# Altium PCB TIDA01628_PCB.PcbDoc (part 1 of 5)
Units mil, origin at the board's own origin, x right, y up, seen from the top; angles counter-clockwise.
Board outline 14212.6 x 5944.88 mil, 4 copper layers (Top Layer, GND, 5V, Bottom Layer), stack 60.8 mil thick; 304 components, 201 nets, 839 pads, 2143 vias.
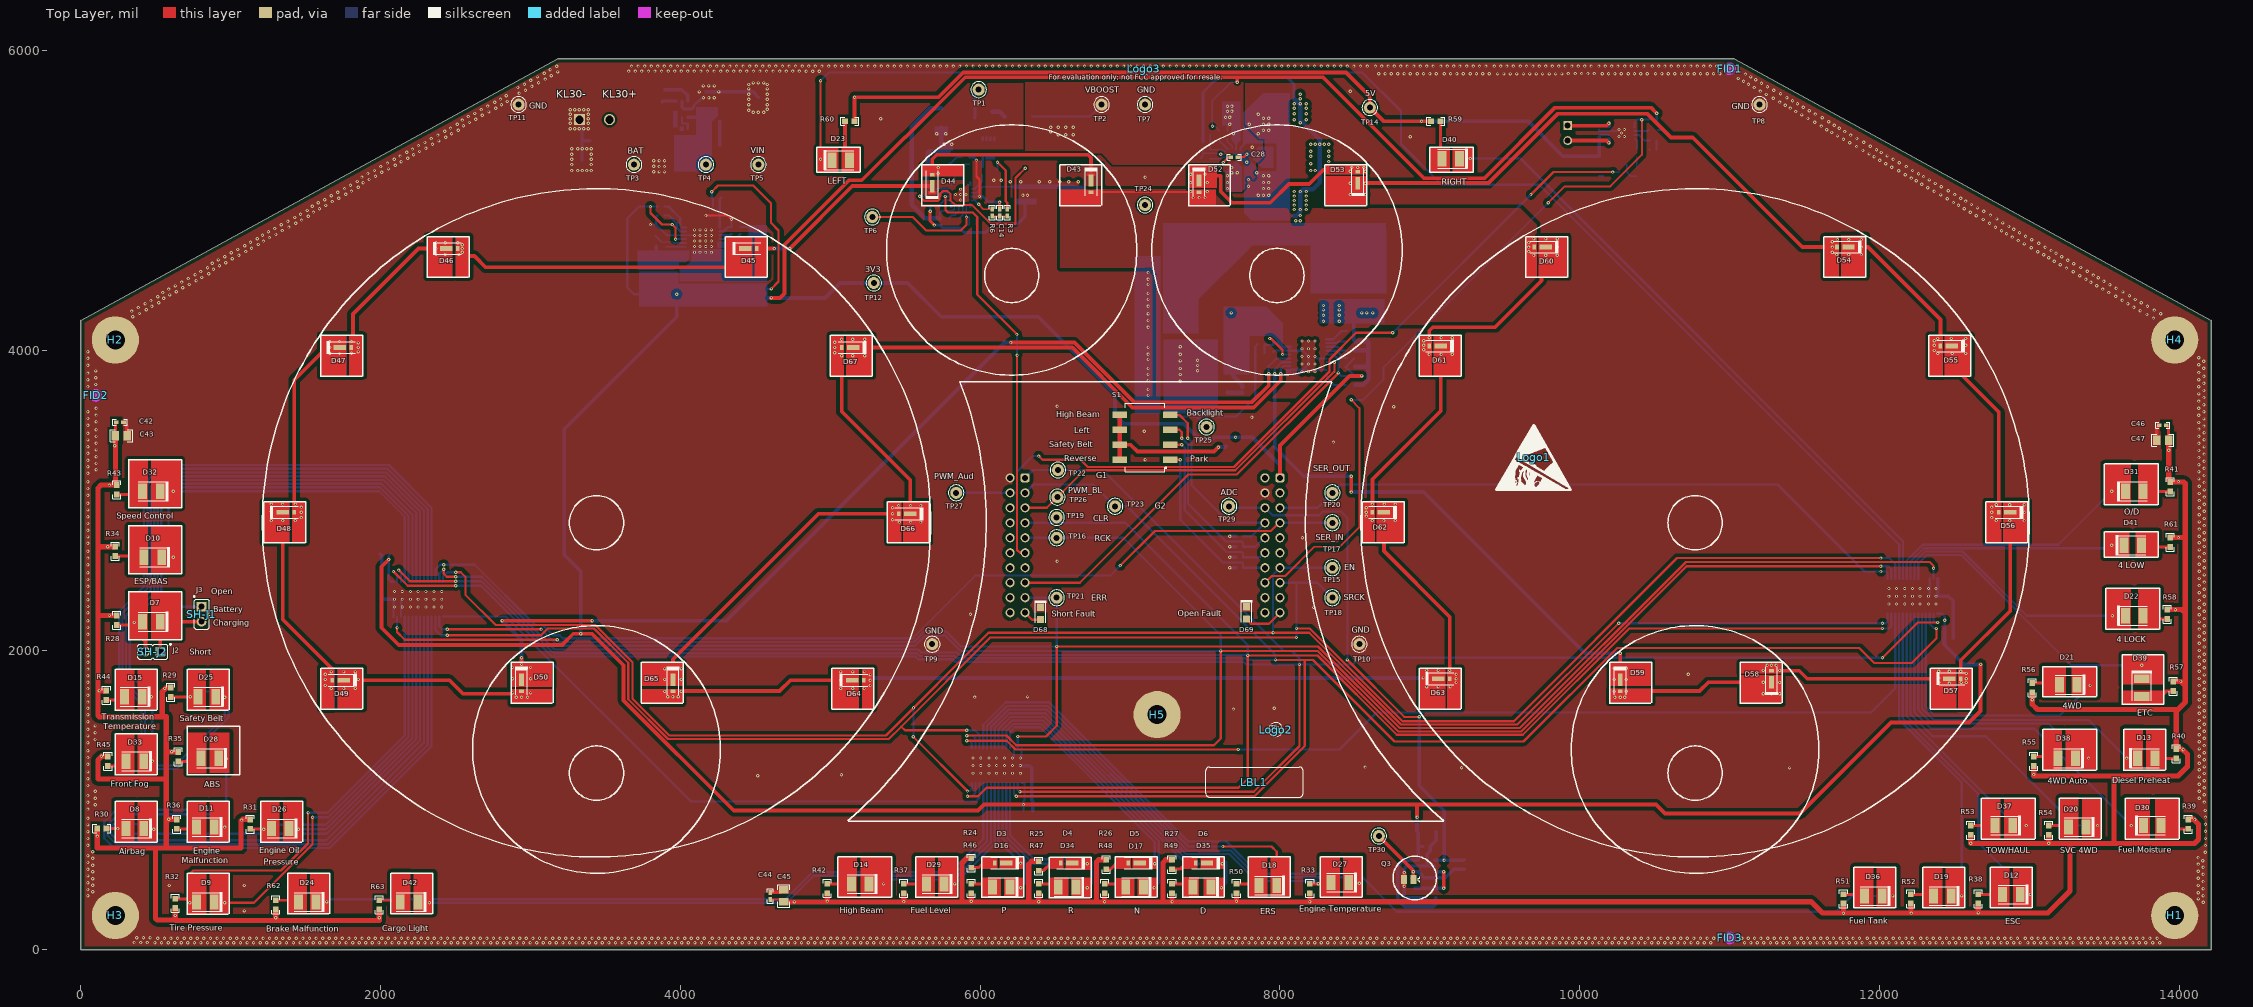
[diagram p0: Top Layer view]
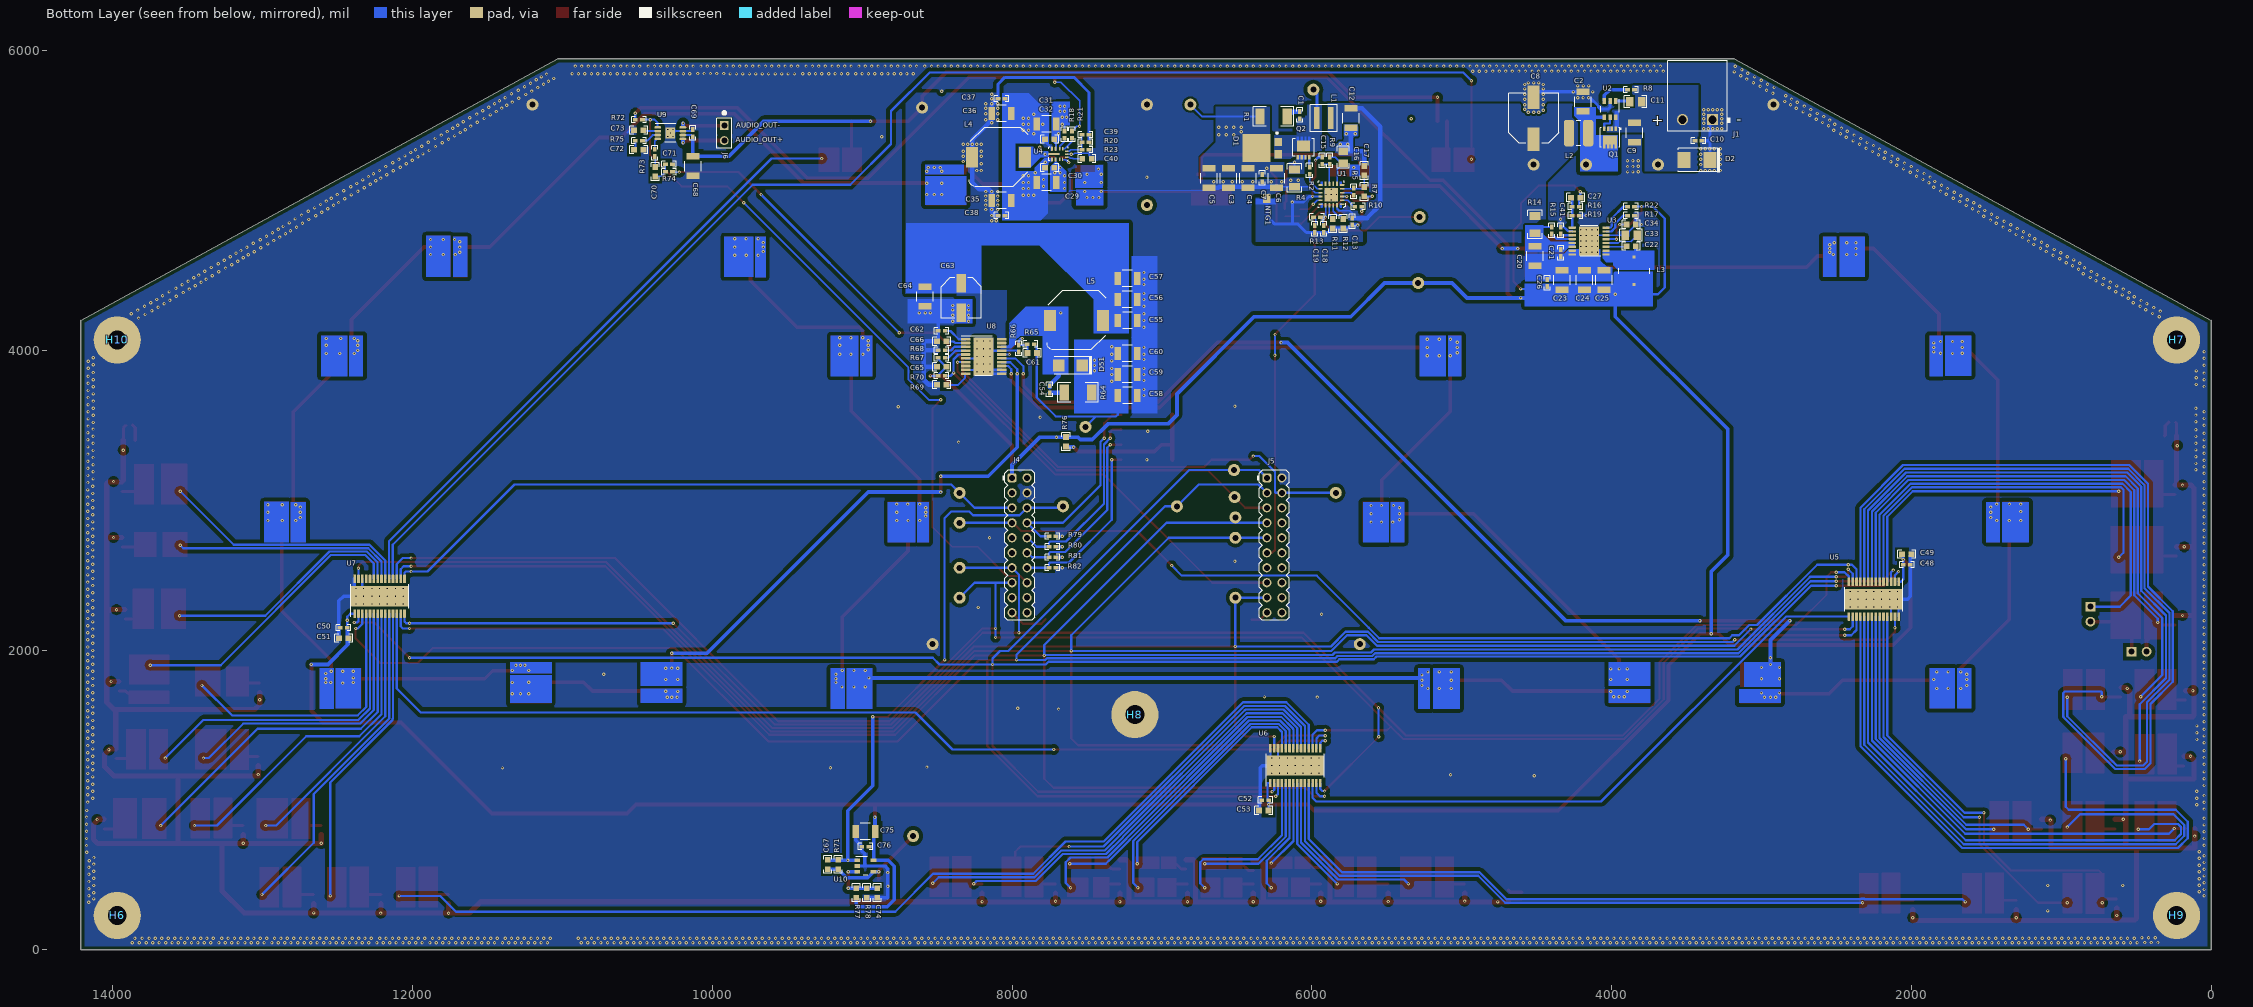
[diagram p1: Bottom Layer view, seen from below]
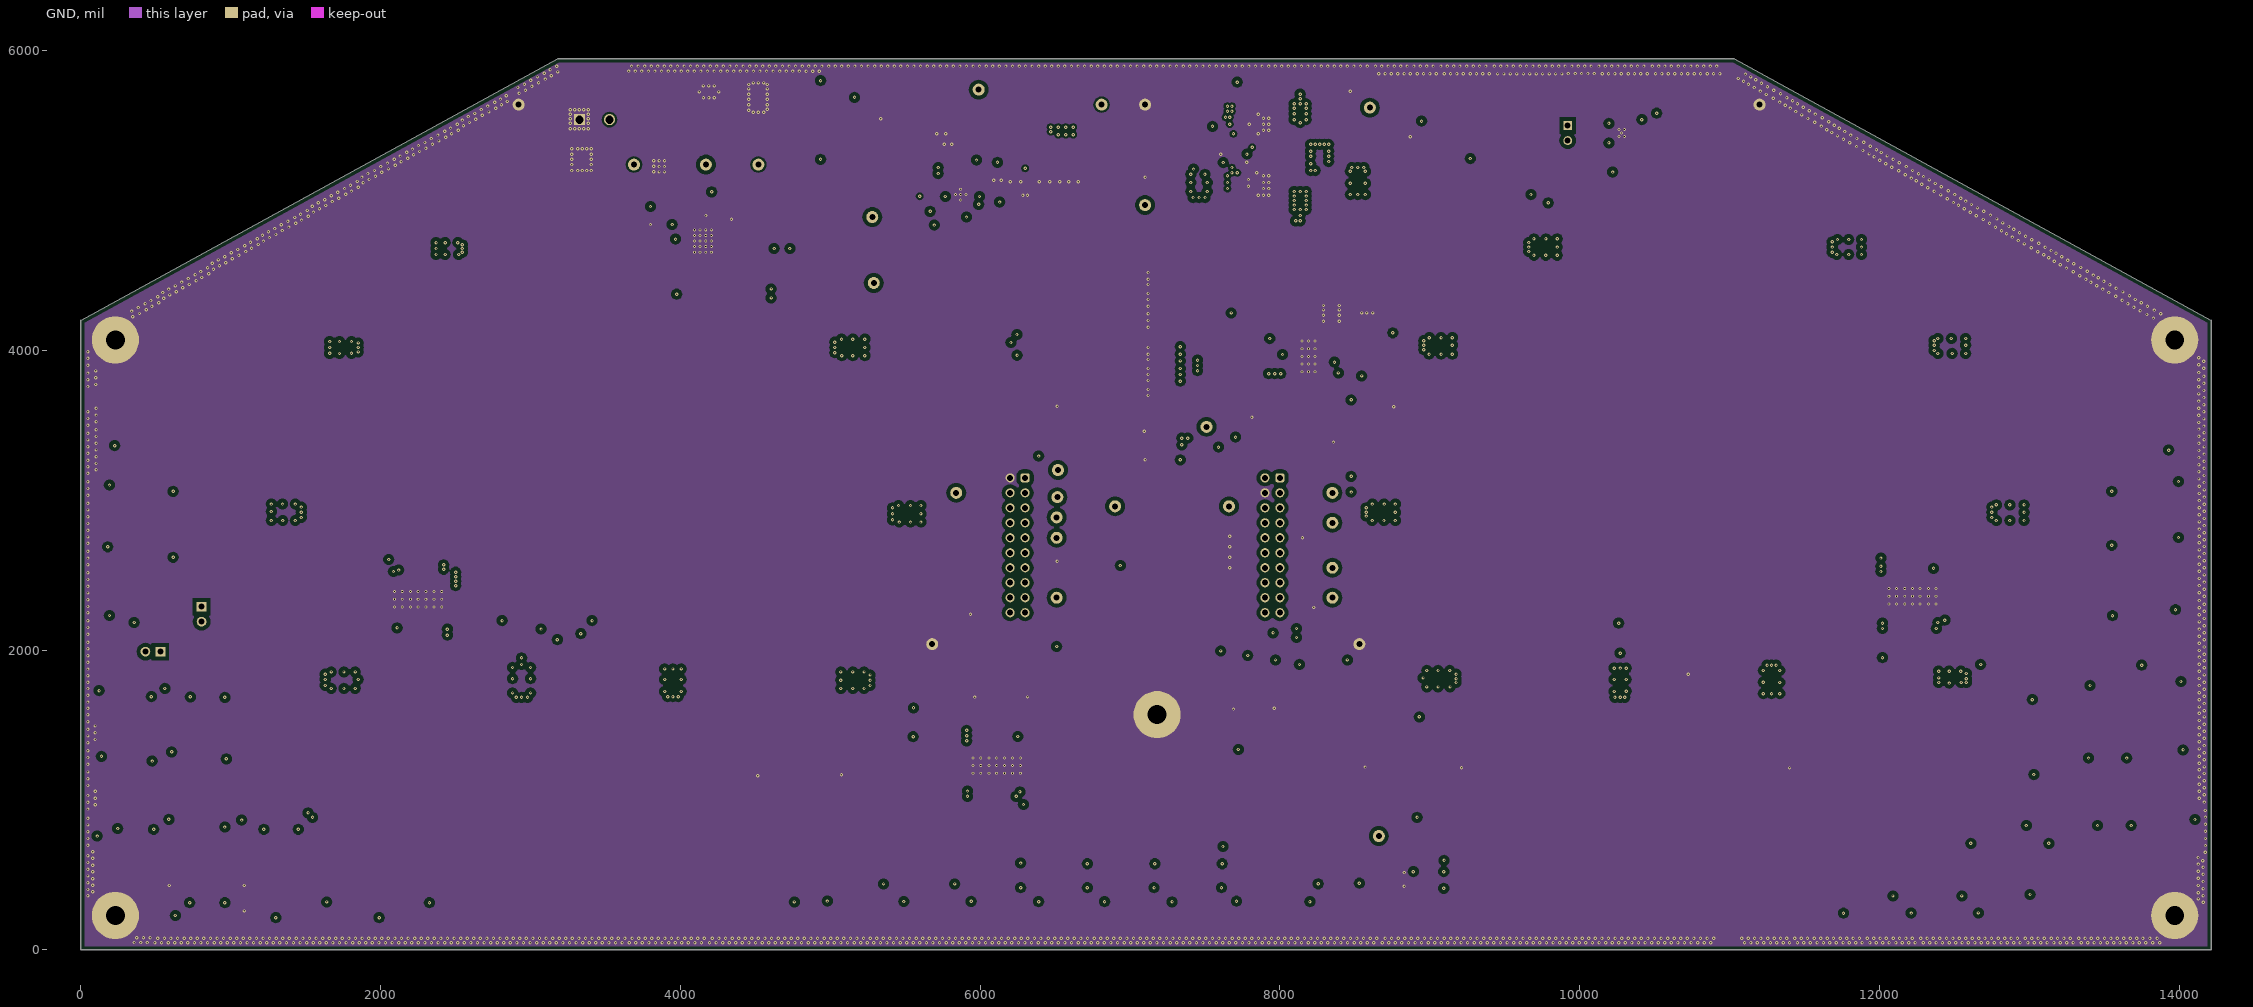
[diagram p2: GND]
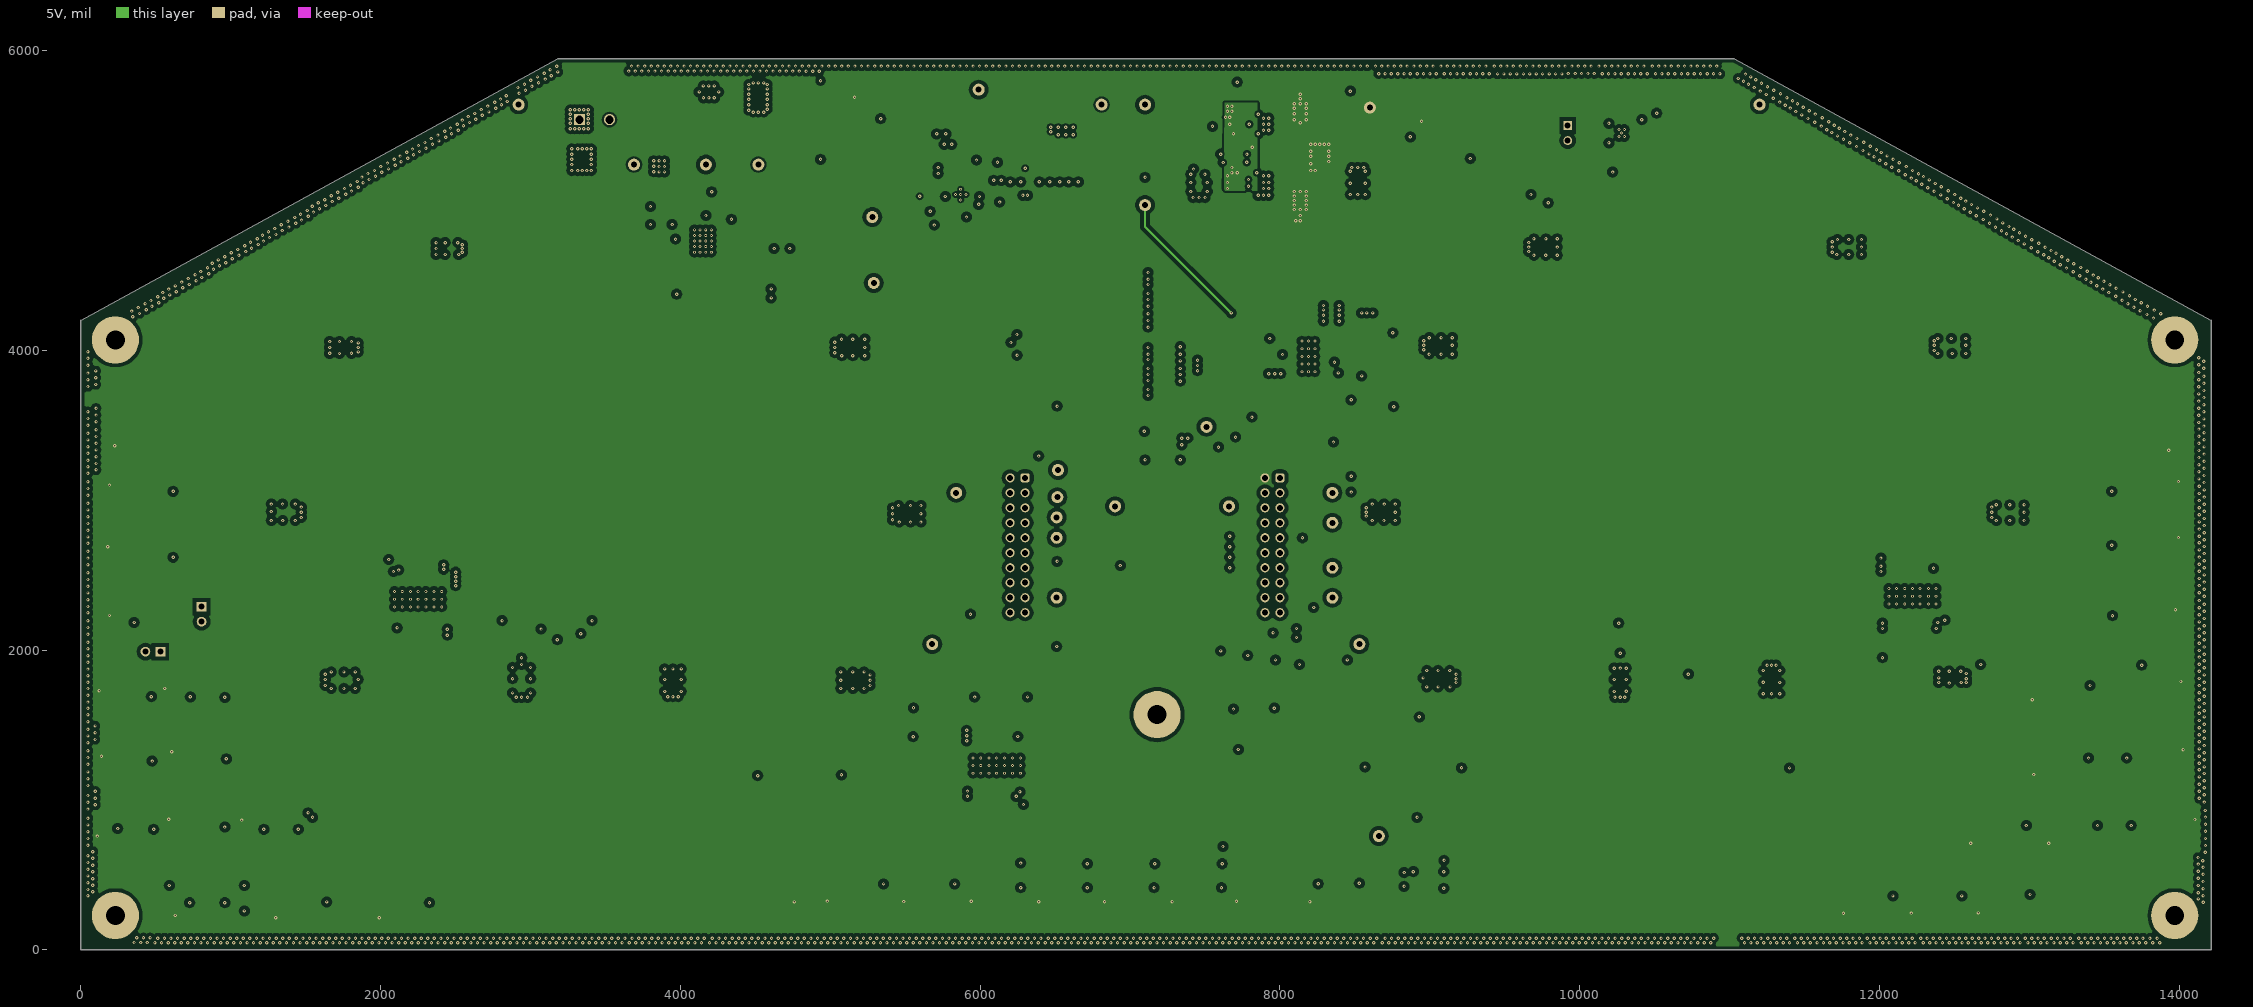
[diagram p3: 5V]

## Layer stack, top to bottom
Top Solder: solder mask 0.4, Solder Resist, Dk 3.5
Top Layer: signal copper 1.9
Pre-Preg: prepreg 11.8, 1080-FR-4 370, Dk 4.2
GND: signal copper 1.2
Core: core 31, FR4 370, Dk 4.2
5V: signal copper 1.2
Pre-Preg: prepreg 11.8, 1080-FR4 370, Dk 4.2
Bottom Layer: signal copper 1.9
Bottom Solder: solder mask 0.4, Solder Resist, Dk 3.5

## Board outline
0,0 0,4200 3179.92,5944.88 11032.68,5944.88 14212.6,4200 14212.6,0

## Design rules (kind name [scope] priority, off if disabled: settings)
AcuteAngle [All] p1: minimum=4.50000000000000E+0001 checktracksonly=FALSE
AssemblyTestPointUsage [All] p1: valid=2
BoardOutlineClearance BoardOutlineClearance_MountingHoles [OnCopper and InComponentClass('Mounting Holes')] p1: gap=40 ignorepadtopadclearanceinfootprint=FALSE
BoardOutlineClearance BoardOutlineClearance_Poly [OnCopper and IsPoly] p2: gap=25 ignorepadtopadclearanceinfootprint=FALSE
Clearance Clearance_Fidicial [HasFootprint('Fiducial10-20')] p1: gap=0 ignorepadtopadclearanceinfootprint=FALSE
Clearance Clearance_0402_COMPONENT [(InComponent('C7') OR InComponent('C10') OR InComponent('C13') OR InComponent('R8') OR InComponent('R18'))] p2: gap=15.74 ignorepadtopadclearanceinfootprint=FALSE
Clearance Clearance_Q1 [InComponent('Q1')] p3: gap=9 ignorepadtopadclearanceinfootprint=FALSE
Clearance Clearance_U1 [InComponent('U1')] p4: gap=11.81 ignorepadtopadclearanceinfootprint=FALSE
Clearance Clearance_U4 [(InNet('VBOOST') AND InComponent('U4'))] p5: gap=11.81 ignorepadtopadclearanceinfootprint=FALSE
Clearance Clearance_U2_1 [(InNet('VIN') OR InNet('VBOOST') OR InNet('KL30_Power') OR InComponent('U2'))] p6: gap=13.7 ignorepadtopadclearanceinfootprint=FALSE
Clearance Clearance_Keepouts [((IsTrack Or IsArc) And Not InPoly) And IsFree and IsKeepOut vs ((IsTrack Or IsArc) And Not InPoly) And IsFree and IsKeepOut] p7: gap=0 ignorepadtopadclearanceinfootprint=FALSE
Clearance Clearance_KL30_POWER [InNet('KL30_Power')] p8: gap=16 ignorepadtopadclearanceinfootprint=FALSE
Clearance Clearance_VBOOST [InNet('VBOOST')] p9: gap=16 ignorepadtopadclearanceinfootprint=FALSE
Clearance Clearance_VIN [InNet('VIN')] p10: gap=16 ignorepadtopadclearanceinfootprint=FALSE
Clearance Clearance_Poly [InPolygon] p11: gap=25 ignorepadtopadclearanceinfootprint=FALSE
Clearance [All] p12: gap=7.87 ignorepadtopadclearanceinfootprint=FALSE except(0: Arc-Hole Track-Hole SMDPad-Hole THPad-Hole Via-Hole Fill-Hole Poly-Hole Region-Hole Text-Hole)
Clearance Clearance_FiducialMark [IsKeepOut and InComponentClass('FiducialMark') vs IsPad and InComponentClass('FiducialMark')] p13: gap=0 ignorepadtopadclearanceinfootprint=FALSE
ComponentClearance ComponentClearance_MountingHoles_FiducialMarks [InComponentClass('Mounting Holes') vs InComponentClass('FiducialMark')] p1: gap=50 collisioncheckmode=3 verticalgap=10 showdistances=FALSE
ComponentClearance ComponentClearance_Shunt [InComponentClass('Header') vs InComponentClass('Shunt')] p2: gap=0 collisioncheckmode=3 verticalgap=0 showdistances=FALSE
ComponentClearance ComponentClearance_Logo [InComponentClass('Logo')] p3: gap=50 collisioncheckmode=3 verticalgap=10 showdistances=FALSE
ComponentClearance ComponentClearance_ScrewToNut [(HasFootprint('NY PMS 440 0025 PH')) vs (HasFootprint('Keystone_1902C'))] p4: gap=5 collisioncheckmode=3 verticalgap=10 showdistances=FALSE
ComponentClearance ComponentClearance_MountingHoles [InComponentClass('Mounting Holes')] p5: gap=250 collisioncheckmode=3 verticalgap=100000 showdistances=FALSE
ComponentClearance ComponentClearance_SmallPassives [HasFootprint('0201*') or HasFootprint('0402*') or HasFootprint('0508') or HasFootprint('0603*') or HasFootprint('0612') or HasFootprint('0805*') or HasFootprint('0815*') or HasFootprint('0830*') or HasFootprint('1206*') or HasFootprint('1210*') or HasFootprint('1808*') or HasFootprint('1812*') or HasFootprint('1825*') or HasFootprint('2010*') or HasFootprint('2220*') or HasFootprint('2225*') or HasFootprint('2512*') or HasFootprint('2728*') or HasFootprint('3518*') vs HasFootprint('0201*') or HasFootprint('0402*') or HasFootprint('0508') or HasFootprint('0603*') or HasFootprint('0612') or HasFootprint('0805*') or HasFootprint('0815*') or HasFootprint('0830*') or HasFootprint('1206*') or HasFootprint('1210*') or HasFootprint('1808*') or HasFootprint('1812*') or HasFootprint('1825*') or HasFootprint('2010*') or HasFootprint('2220*') or HasFootprint('2225*') or HasFootprint('2512*') or HasFootprint('2728*') or HasFootprint('3518*')] p6: gap=14.96 collisioncheckmode=3 verticalgap=10 showdistances=FALSE
ComponentClearance ComponentClearance_THtoSMT [IsThruComponent vs IsSMTComponent] p7: gap=40 collisioncheckmode=3 verticalgap=30 showdistances=FALSE
ComponentClearance ComponentClearance_THtoTH [IsThruComponent vs IsThruComponent] p8: gap=30 collisioncheckmode=3 verticalgap=30 showdistances=FALSE
ComponentClearance [All] p9: gap=30 collisioncheckmode=3 verticalgap=10 showdistances=FALSE
DiffPairsRouting [All] p1: maxlimit=100 minlimit=10 mostfreqgap=10 toplayer_minwidth=15 toplayer_maxwidth=15 toplayer_prefwidth=15 midlayer1_minwidth=15 midlayer1_maxwidth=15 midlayer1_prefwidth=15 midlayer2_minwidth=15 midlayer2_maxwidth=15 midlayer2_prefwidth=15 bottomlayer_minwidth=15 bottomlayer_maxwidth=15 bottomlayer_prefwidth=15 maxuncoupledlength=1000
FabricationTestPointUsage TestPointUsage [All] p1: valid=2 allowmultiple=FALSE
FabricationTestpoint Testpoint [All] p1: side=3 testpointundercomponent=TRUE minsize=40 maxsize=100 preferedsize=60 minholesize=0 maxholesize=40 preferedholesize=32 testpointgrid=1 allowsidetop=TRUE allowsidebottom=TRUE usegrid=TRUE gridtolerance=0.01
FanoutControl Fanout_LCC [IsLCC] p1: bgadir=Out bgaviamode=Centered fanoutstyle=Auto fanoutdirection=Alternating viagrid=1 // Fanout_LCC (Default Rule)
FanoutControl Fanout_BGA [IsBGA] p2: bgadir=Out bgaviamode=Centered fanoutstyle=Auto fanoutdirection=Alternating viagrid=1 // Fanout_BGA (Default Rule)
FanoutControl Fanout_Default [All] p4: bgadir=Out bgaviamode=Centered fanoutstyle=Auto fanoutdirection=Alternating viagrid=1 // Fanout_Default (Default Rule)
FanoutControl Fanout_Small [(CompPinCount < 5)] p5: bgadir=Out bgaviamode=Centered fanoutstyle=Auto fanoutdirection=OutThenIn viagrid=1 // Fanout_Small (Default Rule)
HoleSize [All] p1: absolutevalues=TRUE maxlimit=251 minlimit=7.87 maxpercent=80.000 minpercent=20.000
MinimumAnnularRing MinimumAnnularRing_ThermalPadVias [IsVia and InAnyComponent] p1: minimumring=5.91
MinimumAnnularRing [All] p2: minimumring=6
MinimumSolderMaskSliver MinimumSolderMaskSliver_Logo [InComponentClass('Logo') vs InComponentClass('Logo')] p1: minsoldermaskwidth=0.7
MinimumSolderMaskSliver [All] p2: minsoldermaskwidth=3.94
PlaneConnect [All] p1: planeconnectstyle=Direct reliefexpansion=10 reliefentries=4 reliefconductorwidth=10 reliefairgap=10
PolygonConnect [All] p1: connectstyle=Direct reliefconductorwidth=10 reliefentries=4 polygonreliefangle="90 Angle" airgapwidth=10
RoutingVias ThermalPadVias [IsVia and InAnyComponent] p1: holewidth=7.87 width=19.68 viastyle="Through Hole" minholewidth=7.87 minwidth=19.68 maxholewidth=12.99 maxwidth=23.62
RoutingVias [All] p2: holewidth=16 width=34 viastyle="Through Hole" minholewidth=7.87 minwidth=26 maxholewidth=40 maxwidth=65
ShortCircuit ShortCircuit_U1 [InComponent('U1')] p1: allowed=TRUE
ShortCircuit [All] p2: allowed=FALSE
SilkToBoardRegionClearance [Not ((IsComment or IsDesignator) And (Hide <> 'False')) and not InRegion(1000,500,4000,800)] p1:
SilkToSilkClearance SilkToSilkClearance_Pb-FreeLogo [(HasFootprint('Pb-Free_Overlay_Medium') OR HasFootprint('Pb-Free_Overlay_Small')) vs (HasFootprint('Pb-Free_Overlay_Medium') OR HasFootprint('Pb-Free_Overlay_Small'))] p1: silktosilkclearance=0
SilkToSilkClearance [All] p2: silktosilkclearance=4
SilkToSolderMaskClearance SilkToComponentPadClearance_DIODE [InComponent('D2')or InComponent('D51')or InComponent('D68')or InComponent('D69')] p1: minsilkscreentomaskgap=3 clearancetoexposedcopper=TRUE
SilkToSolderMaskClearance SilkToComponentPadClearance [(IsPad or IsFill or IsRegion) and InAnycomponent] p2: minsilkscreentomaskgap=5 clearancetoexposedcopper=TRUE
SilkToSolderMaskClearance "Silk to Solder Mask Opening" [All] p3: minsilkscreentomaskgap=4 clearancetoexposedcopper=FALSE
SolderMaskExpansion [All] p1: expansion=1.97
Width [All] p1: maxlimit=100 minlimit=6 preferedwidth=10 checkconnectedcopper=TRUE
14 further rules are at their usual default settings.

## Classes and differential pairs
component class AssemblyNote: ZZ1 ZZ2 ZZ3 ZZ4
component class FiducialMark: FID1 FID2 FID3
component class Header: J2 J3 J4 J5 J6
component class Label: LBL1
component class "Mounting Holes": H1 H2 H3 H4 H5
component class SHUNT: SH-J1 SH-J2
component class TIDA01628_Hardware: !PCB1 FID1 FID2 FID3 H1 H2 H3 H4 H5 H6 H7 H8 H9 H10 LBL1 Logo1 Logo2 Logo3 SH-J1 SH-J2 ZZ1 ZZ2 ZZ3 ZZ4
component class TIDA01628_Power: C1 C2 C3 C4 C5 C6 C7 C8 C9 C10 C11 C12 C13 C14 C15 C16 C17 C18 C19 C20 C21 C22 C23 C24 C25 C26 C27 C28 C29 C30 C31 C32 C33 C34 C35 C36 C37 C38 C39 C40 C41 D1 D2 J1 L1 L2 L3 L4 NTG1 Q1 Q2 R1 R2 R3 R4 R5 R6 R7 R8 R9 R10 R11 R12 R13 R14 R15 R16 R17 R18 R19 R20 R21 R22 R23 TP1 TP2 TP3 TP4 TP5 TP6 TP7 TP8 TP9 TP10 TP11 TP12 TP14 U1 U2 U3 U4
component class TIDA01628_Signal: C54 C55 C56 C57 C58 C59 C60 C61 C62 C63 C64 C65 C66 C67 C68 C69 C70 C71 C72 C73 C74 C75 C76 D43 D44 D45 D46 D47 D48 D49 D50 D51 D52 D53 D54 D55 D56 D57 D58 D59 D60 D61 D62 D63 D64 D65 D66 D67 D68 D69 J4 J5 J6 L5 Q3 R64 R65 R66 R67 R68 R69 R70 R71 R72 R73 R74 R75 R76 R77 R78 R79 R80 R81 R82 S1 TP24 TP25 TP26 TP27 TP29 TP30 U8 U9 U10
component class TIDA01628_Telltale: C42 C43 C44 C45 C46 C47 C48 C49 C50 C51 C52 C53 D3 D4 D5 D6 D7 D8 D9 D10 D11 D12 D13 D14 D15 D16 D17 D18 D19 D20 D21 D22 D23 D24 D25 D26 D27 D28 D29 D30 D31 D32 D33 D34 D35 D36 D37 D38 D39 D40 D41 D42 J2 J3 R24 R25 R26 R27 R28 R29 R30 R31 R32 R33 R34 R35 R36 R37 R38 R39 R40 R41 R42 R43 R44 R45 R46 R47 R48 R49 R50 R51 R52 R53 R54 R55 R56 R57 R58 R59 R60 R61 R62 R63 TP15 TP16 TP17 TP18 TP19 TP20 TP21 TP22 TP23 U5 U6 U7

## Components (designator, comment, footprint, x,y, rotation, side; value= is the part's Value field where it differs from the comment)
C1 "DNP" 0402 6080,5570 r270 bottom value=2200pF
C2 "UMK325AB7106KMHT" 1210_280 4190,5660 r90 bottom value=10uF
C3 "UMK325AB7106KMHT" 1210_280 6555,5150 r270 bottom value=10uF
C4 "UMK325AB7106KMHT" 1210_280 6425,5150 r270 bottom value=10uF
C5 "UMK325AB7106KMHT" 1210_280 6685,5150 r270 bottom value=10uF
C6 "UMK325AB7106KMHT" 1210_280 6235.12,5150 r270 bottom value=10uF
C7 "GCM155R71H104KE02D" 0402 6330,5150 r270 bottom value=0.1uF
C8 "EEE-FK1H101P" SM_RADIAL_F 4520,5550 r90 bottom value=100uF
C9 "UMK325AB7106KMHT" 1210_280 3848,5453 r270 bottom value=10uF
C10 "GCM155R71H104KE02D" 0402 3420,5400 r180 bottom value=0.1uF
C11 "C2012X5R1H225K125AB" 0805_HV 3840,5660 r0 bottom value=2.2uF
C12 "UMK325AB7106KMHT" 1210_280 5740,5550 r270 bottom value=10uF
C13 "GCM155R71H104KE02D" 0402 5730,4860 r270 bottom value=0.1uF
C14 "GRM155R71H102KA01D" 0402 6130,4920 r90 top value=1000pF
C15 "GCM155R71H104KE02D" 0402 5930,5266.38 r90 bottom value=0.1uF
C16 "GCM21BR71C475KA73K" 0805_HV 5790,5290 r90 bottom value=4.7uF
C17 "GCM188R71C105KA64D" 0603 5650,5200 r270 bottom value=1uF
C18 "CGA2B2C0G1H151J050BA" 0402 5920,4810 r270 bottom value=150pF
C19 "CGA2B2X7R1H472K050BA" 0402 5980,4810 r270 bottom value=4700pF
C20 "UMK325AB7106KMHT" 1210_280 4510,4630 r270 bottom value=10uF
C21 "GCM155R71H104KE02D" 0402 4340,4650 r270 bottom value=0.1uF
C22 "CGA3E3X7R1H224K080AB" 0603 3870,4695 r180 bottom value=0.22uF
C23 "CGA6P1X7R1C226M250AC" 1210_280 4330,4470 r90 bottom value=22uF
C24 "CGA6P1X7R1C226M250AC" 1210_280 4180,4470 r90 bottom value=22uF
C25 "CGA6P1X7R1C226M250AC" 1210_280 4050,4470 r90 bottom value=22uF
C26 "CGA2B3X7R1H103K050BB" 0402 4430,4450 r90 bottom value=0.01uF
C27 "CGA3E3X7R1H224K080AB" 0603 4240,5020 r0 bottom value=0.22uF
C28 "GCM155R71H104KE02D" 0402 7695,5290 r0 top value=0.1uF
C29 "UMK325AB7106KMHT" 1210_280 7770,5120 r0 bottom value=10uF
C30 "CGA3E3X7R1H224K080AB" 0603 7750,5220 r0 bottom value=0.22uF
C31 "UMK325AB7106KMHT" 1210_280 7770,5510 r0 bottom value=10uF
C32 "CGA3E3X7R1H224K080AB" 0603 7750,5410 r0 bottom value=0.22uF
C33 "GCM21BR71C475KA73K" 0805_HV 3870,4770 r180 bottom value=4.7uF
C34 "GCM188R71C105KA64D" 0603 3870,4840 r180 bottom value=1uF
C35 "CGA6P1X7R1C226M250AC" 1210_280 8070,5000 r180 bottom value=22uF
C36 "CGA6P1X7R1C226M250AC" 1210_280 8070,5580 r180 bottom value=22uF
C37 "GCM155R71H104KE02D" 0402 8070,5680 r180 bottom value=0.1uF
C38 "GCM155R71H104KE02D" 0402 8070,4900 r180 bottom value=0.1uF
C39 "CGA2B3X7R1H103K050BB" 0402 7510,5440 r0 bottom value=0.01uF
C40 "GCM188R71C105KA64D" 0603 7500,5280 r180 bottom value=1uF
C41 "CGA2B3X7R1H153K050BB" 0402 4340,4800 r90 bottom value=0.015uF
C42 "GCM155R71H104KE02D" 0402 260,3520 r0 top value=0.1uF
C43 "GCM21BR71C475KA73K" 0805_HV 270,3430 r0 top value=4.7uF
C44 "GCM155R71H104KE02D" 0402 4600,360 r90 top value=0.1uF
C45 "GCM21BR71C475KA73K" 0805_HV 4690,360 r90 top value=4.7uF
C46 "GCM155R71H104KE02D" 0402 13890,3500 r180 top value=0.1uF
C47 "GCM21BR71C475KA73K" 0805_HV 13890,3400 r180 top value=4.7uF
C48 "GCM155R71H104KE02D" 0402 2030,2570 r180 bottom value=0.1uF
C49 "GCM188R71C105KA64D" 0603 2030,2640 r180 bottom value=1uF
C50 "GCM155R71H104KE02D" 0402 12460,2150 r0 bottom value=0.1uF
C51 "GCM188R71C105KA64D" 0603 12460,2080 r0 bottom value=1uF
C52 "GCM155R71H104KE02D" 0402 6310,1000 r0 bottom value=0.1uF
C53 "GCM188R71C105KA64D" 0603 6320,930 r0 bottom value=1uF
C54 "DNP" 0402 7750,3740 r90 bottom value=2200pF
C55 "UMK325AB7106KMHT" 1210_280 7230,4200 r180 bottom value=10uF
C56 "UMK325AB7106KMHT" 1210_280 7230.31,4339.69 r180 bottom value=10uF
C57 "UMK325AB7106KMHT" 1210_280 7230.31,4479.69 r180 bottom value=10uF
C58 "UMK325AB7106KMHT" 1210_280 7230,3700 r180 bottom value=10uF
C59 "UMK325AB7106KMHT" 1210_280 7230.31,3839.69 r180 bottom value=10uF
C60 "UMK325AB7106KMHT" 1210_280 7230.31,3979.69 r180 bottom value=10uF
C61 "06035A4R7CAT2A" 0603 7866,3982.8 r0 bottom value=4.7pF
C62 "GCM155R71H104KE02D" 0402 8470,4130 r0 bottom value=0.1uF
C63 "EEE-FK1V330P" SM_RADIAL_D 8340,4350 r270 bottom value=33uF
C64 "UMK325AB7106KMHT" 1210_280 8580,4360 r270 bottom value=10uF
C65 "GCM188R71C105KA64D" 0603 8470,3890 r0 bottom value=1uF
C66 "GCM188R71C105KA64D" 0603 8469.69,4060 r0 bottom value=1uF
C67 "C1608C0G1H101J080AE" 0603 9228.7,570 r270 bottom value=100pF
C68 "UMK325AB7106KMHT" 1210_280 10130,5230 r270 bottom value=10uF
C69 "GCM155R71H104KE02D" 0402 10130,5450 r90 bottom value=0.1uF
C70 "GCM188R71C474KA55D" 0603 10380,5193 r270 bottom value=0.47uF
C71 "GCM155R71E103KA37D" 0402 10289,5242 r180 bottom value=0.01uF
C72 "GCM188R71C474KA55D" 0603 10490,5340 r180 bottom value=0.47uF
C73 "CGA3E3X7R1H224K080AB" 0603 10490,5470 r0 bottom value=0.22uF
C74 "GCM188R71C105KA64D" 0603 8898.7,380 r270 bottom value=1uF
C75 "UMK325AB7106KMHT" 1210_280 8978.7,790 r0 bottom value=10uF
C76 "GCM155R71H104KE02D" 0402 8978.7,690 r0 bottom value=0.1uF
D1 "V10P6-M3/87A" TO-277A 6295.12,5350 r270 bottom value=60V
D2 "SMBJ33CA-13-F" SMB 3430,5270 r0 bottom value=33V
D3 "KW DPLS32.EC-6H6J-4F8G-1" KW_DPLS32_EC_White 6150,580 r0 top value=White
D4 "KW DPLS32.EC-6H6J-4F8G-1" KW_DPLS32_EC_White 6590,580 r0 top value=White
D5 "KW DPLS32.EC-6H6J-4F8G-1" KW_DPLS32_EC_White 7040,580 r0 top value=White
D6 "KW DPLS32.EC-6H6J-4F8G-1" KW_DPLS32_EC_White 7490,580 r0 top value=White
D7 "LS T67K-J1L2-1-Z" LS_T67K_Red 470,2190 r90 top value=Red
D8 "LS T67K-J1L2-1-Z" LS_T67K_Red 360,810 r90 top value=Red
D9 "LS T67K-J1L2-1-Z" LS_T67K_Red 830,320 r90 top value=Red
D10 "LY T67K-J2M1-26-Z" LY_T67K_Yellow 480,2620 r90 top value=Yellow
D11 "LY T67K-J2M1-26-Z" LY_T67K_Yellow 830,820 r90 top value=Yellow
D12 "LY T67K-J2M1-26-Z" LY_T67K_Yellow 12880,370 r90 top value=Yellow
D13 "LY T67K-J2M1-26-Z" LY_T67K_Yellow 13780,1280 r270 top value=Yellow
D14 "LB T673-L2P1-25-Z" LB_T673_Blue 5200,440 r90 top value=Blue
D15 "LG T67K-G2K1-24-Z" LG_T67K_Green 350,1690 r90 top value=Green
D16 "LG T67K-G2K1-24-Z" LG_T67K_Green 6140,420 r90 top value=Green
D17 "LG T67K-G2K1-24-Z" LG_T67K_Green 7030,420 r90 top value=Green
D18 "LG T67K-G2K1-24-Z" LG_T67K_Green 7920,430 r90 top value=Green
D19 "LG T67K-G2K1-24-Z" LG_T67K_Green 12420,360 r90 top value=Green
D20 "LG T67K-G2K1-24-Z" LG_T67K_Green 13320,820 r90 top value=Green
D21 "LG T67K-G2K1-24-Z" LG_T67K_Green 13260,1770 r90 top value=Green
D22 "LG T67K-G2K1-24-Z" LG_T67K_Green 13700,2230 r270 top value=Green
D23 "LG T67K-G2K1-24-Z" LG_T67K_Green 5070,5270 r270 top value=Green
D24 "LG T67K-G2K1-24-Z" LG_T67K_Green 1510,320 r90 top value=Green
D25 "LS T67K-J1L2-1-Z" LS_T67K_Red 840,1690 r90 top value=Red
D26 "LS T67K-J1L2-1-Z" LS_T67K_Red 1330,810 r90 top value=Red
D27 "LS T67K-J1L2-1-Z" LS_T67K_Red 8400,450 r90 top value=Red
D28 "LY T67K-J2M1-26-Z" LY_T67K_Yellow 860,1280 r90 top value=Yellow
D29 "LY T67K-J2M1-26-Z" LY_T67K_Yellow 5700,440 r90 top value=Yellow
D30 "LY T67K-J2M1-26-Z" LY_T67K_Yellow 13820,830 r270 top value=Yellow
D31 "LY T67K-J2M1-26-Z" LY_T67K_Yellow 13700,3060 r270 top value=Yellow
D32 "LG T67K-G2K1-24-Z" LG_T67K_Green 470,3060 r90 top value=Green
D33 "LG T67K-G2K1-24-Z" LG_T67K_Green 360,1260 r90 top value=Green
D34 "LG T67K-G2K1-24-Z" LG_T67K_Green 6580,420 r90 top value=Green
D35 "LG T67K-G2K1-24-Z" LG_T67K_Green 7480,420 r90 top value=Green
D36 "LG T67K-G2K1-24-Z" LG_T67K_Green 11960,360 r90 top value=Green
D37 "LG T67K-G2K1-24-Z" LG_T67K_Green 12830,830 r90 top value=Green
D38 "LG T67K-G2K1-24-Z" LG_T67K_Green 13250,1280 r90 top value=Green
D39 "LG T67K-G2K1-24-Z" LG_T67K_Green 13750,1750 r180 top value=Green
D40 "LG T67K-G2K1-24-Z" LG_T67K_Green 9140,5280 r90 top value=Green
D41 "LG T67K-G2K1-24-Z" LG_T67K_Green 13690,2700 r270 top value=Green
D42 "LG T67K-G2K1-24-Z" LG_T67K_Green 2190,320 r90 top value=Green
D43 "KW DPLS32.EC-6H6J-4F8G-1" KW_DPLS32_EC_White 6740,5110 r90 top value=White
D44 "KW DPLS32.EC-6H6J-4F8G-1" KW_DPLS32_EC_White 5680,5120 r270 top value=White
D45 "KW DPLS32.EC-6H6J-4F8G-1" KW_DPLS32_EC_White 4457.01,4680 r180 top value=White
D46 "KW DPLS32.EC-6H6J-4F8G-1" KW_DPLS32_EC_White 2460,4680 r180 top value=White
D47 "KW DPLS32.EC-6H6J-4F8G-1" KW_DPLS32_EC_White 1750,4020 r180 top value=White
D48 "KW DPLS32.EC-6H6J-4F8G-1" KW_DPLS32_EC_White 1370,2920 r180 top value=White
D49 "KW DPLS32.EC-6H6J-4F8G-1" KW_DPLS32_EC_White 1730,1800 r0 top value=White
D50 "KW DPLS32.EC-6H6J-4F8G-1" KW_DPLS32_EC_White 2940,1780 r90 top value=White
D51 "SSA36" SMA 7610,3900 r0 bottom value=60V
D52 "KW DPLS32.EC-6H6J-4F8G-1" KW_DPLS32_EC_White 7460,5110 r90 top value=White
D53 "KW DPLS32.EC-6H6J-4F8G-1" KW_DPLS32_EC_White 8520,5140 r270 top value=White
D54 "KW DPLS32.EC-6H6J-4F8G-1" KW_DPLS32_EC_White 11770,4690 r0 top value=White
D55 "KW DPLS32.EC-6H6J-4F8G-1" KW_DPLS32_EC_White 12460,4030 r0 top value=White
D56 "KW DPLS32.EC-6H6J-4F8G-1" KW_DPLS32_EC_White 12850,2920 r0 top value=White
D57 "KW DPLS32.EC-6H6J-4F8G-1" KW_DPLS32_EC_White 12490,1810 r180 top value=White
D58 "KW DPLS32.EC-6H6J-4F8G-1" KW_DPLS32_EC_White 11280,1810 r270 top value=White
D59 "KW DPLS32.EC-6H6J-4F8G-1" KW_DPLS32_EC_White 10270,1780 r90 top value=White
D60 "KW DPLS32.EC-6H6J-4F8G-1" KW_DPLS32_EC_White 9750,4690 r0 top value=White
D61 "KW DPLS32.EC-6H6J-4F8G-1" KW_DPLS32_EC_White 9050,4030 r0 top value=White
D62 "KW DPLS32.EC-6H6J-4F8G-1" KW_DPLS32_EC_White 8670,2920 r0 top value=White
D63 "KW DPLS32.EC-6H6J-4F8G-1" KW_DPLS32_EC_White 9080,1810 r180 top value=White
D64 "KW DPLS32.EC-6H6J-4F8G-1" KW_DPLS32_EC_White 5170,1800 r180 top value=White
D65 "KW DPLS32.EC-6H6J-4F8G-1" KW_DPLS32_EC_White 3950,1780 r90 top value=White
D66 "KW DPLS32.EC-6H6J-4F8G-1" KW_DPLS32_EC_White 5510,2910 r0 top value=White
D67 "KW DPLS32.EC-6H6J-4F8G-1" KW_DPLS32_EC_White 5130,4020 r0 top value=White
D68 "LTST-C170KRKT" LED_LTST-C170_Red 6402,2245 r90 top value=Red
D69 "LTST-C170KRKT" LED_LTST-C170_Red 7776.77,2248.25 r90 top value=Red
FID1 "Fiducial" Fiducial10-20 11000,5880 r90 top
FID2 "Fiducial" Fiducial10-20 100,3700 r90 top
FID3 "Fiducial" Fiducial10-20 11000,80 r90 top
H1 "NY PMS 440 0025 PH" "NY PMS 440 0025 PH" 13970,230 r0 top locked
H2 "NY PMS 440 0025 PH" "NY PMS 440 0025 PH" 230,4070 r0 top locked
H3 "NY PMS 440 0025 PH" "NY PMS 440 0025 PH" 230,230 r0 top locked
H4 "NY PMS 440 0025 PH" "NY PMS 440 0025 PH" 13970,4070 r0 top
H5 "NY PMS 440 0025 PH" "NY PMS 440 0025 PH" 7180.23,1569.99 r0 top
H6 "1902C" Keystone_1902C 13969.77,230.01 r180 bottom
H7 "1902C" Keystone_1902C 230,4070 r180 bottom
H8 "1902C" Keystone_1902C 7180,1570 r180 bottom locked
H9 "1902C" Keystone_1902C 229.77,230.01 r180 bottom
H10 "1902C" Keystone_1902C 13970,4070 r0 bottom locked
J1 "1759017" Phoenix_1759017 3426.55,5540 r0 bottom
J2 "PBC02SAAN" Sullins_PBC02SAAN 480,1990 r270 top
J3 "PBC02SAAN" Sullins_PBC02SAAN 805.09,2240 r0 top
J4 "PEC10DAAN" SULLINS_PEC10DAAN 7950,2700 r180 bottom locked
J5 "PEC10DAAN" SULLINS_PEC10DAAN 6250,2700 r180 bottom locked
J6 "5-146261-1" CONN_5-146261-1 9920,5450 r270 bottom
L1 "XEL4020-561MEB" XEL4020 5920,5550 r0 bottom value=560nH
L2 "7447730" WE-PD2-S 4220,5450 r0 bottom value=1uH
L3 "7440430018" WE-TPC_4828 3850,4530 r270 bottom value=1.8uH
L4 "7447713015" WE-PD_1030 8090,5290 r0 bottom value=1.5uH
L5 "7447713047" WE-PD_1030 7570,4200 r0 bottom value=4.7uH
LBL1 "THT-14-423-10" Label_650x200 7830,1120 r180 top
Logo1 "ESD Susceptible" ESD_Overlay_Large 9693,3286 r0 top
Logo2 "Pb-Free Symbol" Pb-Free_Overlay_Small 7972,1470 r0 top
Logo3 "FCC disclaimer" FCC_disclaimer 7090,5880 r0 top
NTG1 "Net-Tie" Net-Tie_50milWide_30milLong 6300,5015 r90 bottom net-tie
Q1 "DMT6007LFG-13" PowerDI3333-8 4010,5420 r270 bottom value=60V
Q2 "BUK9M85-60EX" TRANS_NXP_LFPAK33 6055.12,5350 r90 bottom value=60V
Q3 "TEMT6200FX01" VISHAY_TEMT6200FX01 8860,470 r0 top value=550nm
R1 "DNP" 2010 6255.12,5560 r0 bottom value=2.0
R2 "CRCW04020000Z0ED" 0402 6015.12,5200 r90 bottom value=0
R3 "CRCW040249R9FKED" 0402 6180,4920 r90 top value=49.9
R4 "WSLP1206R0150FEA" 1206 6115.12,5150 r90 bottom value=0.015
R5 "CRCW04020000Z0ED" 0402 5720,5060 r270 bottom value=0
R6 "CRCW04020000Z0ED" 0402 6080,4920 r270 top value=0
R7 "RC0603FR-072RL" 0603 5650,5060 r270 bottom value=2.00
R8 "CRCW04020000Z0ED" 0402 3870,5740 r0 bottom value=0
R9 "CRCW040210R0FKED" 0402 5880,5266.38 r90 bottom value=10.0
R10 "CRCW04020000Z0ED" 0402 5690,4960 r0 bottom value=0
R11 "CRCW06039K53FKEA" 0603 5860,4845 r90 bottom value=9.53k
R12 "CRCW06039K53FKEA" 0603 5790,4845 r90 bottom value=9.53k
R13 "CRCW04024K02FKED" 0402 5965,4890 r180 bottom value=4.02k
R14 "CRCW12060000Z0EA" 1206 4510,4840 r270 bottom value=0
R15 "CRCW04020000Z0ED" 0402 4400,4800 r270 bottom value=0
R16 "CRCW0402100KFKED" 0402 4240,4960 r180 bottom value=100k
R17 "CRCW040218K0FKED" 0402 3870,4900 r0 bottom value=18.0k
R18 "CRCW04020000Z0ED" 0402 7650,5440 r90 bottom value=0
R19 "CRCW040243K2FKED" 0402 4240,4900 r0 bottom value=43.2k
R20 "CRCW0402100KFKED" 0402 7510,5390 r180 bottom value=100k
R21 "CRCW040211K0FKED" 0402 7600,5440 r90 bottom value=11.0k
R22 "CRCW040211K0FKED" 0402 3870,4960 r180 bottom value=11.0k
R23 "CRCW040224K9FKED" 0402 7510,5340 r0 bottom value=24.9k
R24 "CRCW060368R0JNEA" 0603 5940,580 r90 top value=68
R25 "CRCW060368R0JNEA" 0603 6390,560 r90 top value=68
R26 "CRCW060368R0JNEA" 0603 6840,570 r90 top value=68
R27 "CRCW060368R0JNEA" 0603 7280,570 r90 top value=68
R28 "CRCW0603130RFKEA" 0603 240,2200 r90 top value=130
R29 "CRCW0603130RFKEA" 0603 600,1720 r90 top value=130
R30 "CRCW0603130RFKEA" 0603 140,810 r180 top value=130
R31 "CRCW0603130RFKEA" 0603 1130,840 r90 top value=130
R32 "CRCW0603130RFKEA" 0603 630,310 r270 top value=130
R33 "CRCW0603130RFKEA" 0603 8200,410 r270 top value=130
R34 "CRCW0603130RFKEA" 0603 230,2660 r90 top value=130
R35 "CRCW0603130RFKEA" 0603 650,1290 r90 top value=130
R36 "CRCW0603130RFKEA" 0603 640,840 r90 top value=130
R37 "CRCW0603130RFKEA" 0603 5490,410 r270 top value=130
R38 "CRCW0603130RFKEA" 0603 12660,340 r270 top value=130
R39 "CRCW0603130RFKEA" 0603 14060,840 r90 top value=130
R40 "CRCW0603130RFKEA" 0603 13980,1310 r90 top value=130
R41 "CRCW0603130RFKEA" 0603 13940,3090 r90 top value=130
R42 "CRCW060375R0JNEA" 0603 4980,410 r270 top value=75
R43 "CRCW0603130RFKEA" 0603 240,3070 r90 top value=130
R44 "CRCW0603130RFKEA" 0603 170,1700 r90 top value=130
R45 "CRCW0603130RFKEA" 0603 180,1260 r90 top value=130
R46 "CRCW0603130RFKEA" 0603 5940,410 r270 top value=130
R47 "CRCW0603130RFKEA" 0603 6390,410 r270 top value=130
R48 "CRCW0603130RFKEA" 0603 6830,410 r270 top value=130
R49 "CRCW0603130RFKEA" 0603 7280,410 r270 top value=130
R50 "CRCW0603130RFKEA" 0603 7710,410 r270 top value=130
R51 "CRCW0603130RFKEA" 0603 11760,340 r270 top value=130
R52 "CRCW0603130RFKEA" 0603 12210,340 r270 top value=130
R53 "CRCW0603130RFKEA" 0603 12610,800 r270 top value=130
R54 "CRCW0603130RFKEA" 0603 13130,800 r270 top value=130
R55 "CRCW0603130RFKEA" 0603 13030,1260 r270 top value=130
R56 "CRCW0603130RFKEA" 0603 13020,1750 r270 top value=130
R57 "CRCW0603130RFKEA" 0603 13960,1760 r90 top value=130
R58 "CRCW0603130RFKEA" 0603 13920,2240 r90 top value=130
R59 "CRCW0603130RFKEA" 0603 9040,5530 r180 top value=130
R60 "CRCW0603130RFKEA" 0603 5130,5530 r0 top value=130
R61 "CRCW0603130RFKEA" 0603 13940,2720 r90 top value=130
R62 "CRCW0603130RFKEA" 0603 1300,300 r270 top value=130
R63 "CRCW0603130RFKEA" 0603 1990,300 r270 top value=130
R64 "DNP" 2010 7560,3720 r180 bottom value=2.0
R65 "CRCW0402681KFKED" 0402 7876,4042.8 r180 bottom value=681k
R66 "CRCW0402130KFKED" 0402 7956,4012.8 r90 bottom value=130k
R67 "CRCW04020000Z0ED" 0402 8470,3950 r0 bottom value=0
R68 "CRCW040224K0JNED" 0402 8470,4000 r180 bottom value=24k
R69 "CRCW060330K1FKEA" 0603 8470,3770 r0 bottom value=30.1k
R70 "CRCW040251K0JNED" 0402 8470,3830 r180 bottom value=51k
R71 "CRCW06031K47FKEA" 0603 9158.7,570 r90 bottom value=1.47k
R72 "CRCW040251K0JNED" 0402 10490,5540 r0 bottom value=51k
R73 "CRCW040212K4FKED" 0402 10383.23,5318.16 r270 bottom value=12.4k
R74 "CRCW04021K58FKED" 0402 10289,5191 r0 bottom value=1.58k
R75 "CRCW040212K4FKED" 0402 10490,5400 r180 bottom value=12.4k
R76 "ERJ-3EKF1000V" 0603 7640,3390 r90 bottom value=100
R77 "CRCW06036K34FKEA" 0603 9038.7,380 r270 bottom value=6.34k
R78 "CRCW0603634RFKEA" 0603 8968.7,380 r90 bottom value=634
R79 "CRCW040251K0JNED" 0402 7730,2760 r0 bottom value=51k
R80 "CRCW040251K0JNED" 0402 7730,2690 r0 bottom value=51k
R81 "CRCW040251K0JNED" 0402 7730,2620 r0 bottom value=51k
R82 "CRCW040251K0JNED" 0402 7730,2550 r0 bottom value=51k
S1 "219-4MST" SW_219-4MST 7100,3420 r180 top
SH-J1 "M7582-05" Harwin_M7582-05 805.09,2240 r90 top
SH-J2 "M7582-05" Harwin_M7582-05 480,1990 r180 top
TP1 "5002" Keystone5002 5990,5740 r0 top
TP2 "5000" Keystone5000 6810,5640 r90 top
TP3 "5000" Keystone5000 3690,5240 r90 top
TP4 "5000" Keystone5000 4170,5240 r90 top
TP5 "5000" Keystone5000 4520,5240 r90 top
TP6 "5002" Keystone5002 5280,4890 r0 top
TP7 "5000" Keystone5000 7100,5640 r90 top
TP8 "5000" Keystone5000 11200,5640 r90 top
TP9 "5000" Keystone5000 5680,2040 r90 top
TP10 "5000" Keystone5000 8530,2040 r90 top
TP11 "5000" Keystone5000 2920,5640 r90 top
TP12 "5000" Keystone5000 5290,4450 r90 top
TP14 "5000" Keystone5000 8600,5620 r90 top
TP15 "5002" Keystone5002 8350,2550 r90 top
TP16 "5002" Keystone5002 6510,2750 r90 top
TP17 "5002" Keystone5002 8350,2850 r90 top
TP18 "5002" Keystone5002 8350,2350 r90 top
TP19 "5002" Keystone5002 6510,2886 r90 top
TP20 "5002" Keystone5002 8350,3050 r90 top
TP21 "5002" Keystone5002 6510,2350 r90 top
TP22 "5002" Keystone5002 6519,3202 r90 top
TP23 "5002" Keystone5002 6900,2960 r90 top
TP24 "5002" Keystone5002 7100,4970 r90 top
TP25 "5000" Keystone5000 7510,3490 r90 top
TP26 "5002" Keystone5002 6515,3021 r90 top
TP27 "5000" Keystone5000 5840,3050 r90 top
TP29 "5000" Keystone5000 7660,2960 r90 top
TP30 "5002" Keystone5002 8660,760 r90 top
U1 "LM5150QRUMTQ1" RUM0016C 5870,5040 r0 bottom
U2 "LM74700QDBVTQ1" DBV0006A_N 4010,5610 r270 bottom
U3 "LM43602QPWPRQ1" PWP0016G_L 4150,4730 r0 bottom
U4 "LMR33630CQRNXRQ1" RNX0012A 7690,5310 r90 bottom
U5 "TLC6C5816QPWPRQ1" PWP0028C_N 2250,2340 r270 bottom
U6 "TLC6C5816QPWPRQ1" PWP0028C_N 6110,1230 r90 bottom
U7 "TLC6C5816QPWPRQ1" PWP0028C_N 12220,2360 r90 bottom
U8 "TPS61193PWPRQ1" PWP0020D_M 8190,3960 r180 bottom
U9 "TPA6211A1TDGNRQ1" DGN0008D_L 10280,5450 r180 bottom
U10 "OPA320AQDBVRQ1" DBV0005A_N 8978.7,560 r180 bottom
ZZ1 "This Assembly Note is for PCB labels only" AssemblyNoteLabel 3260.6,6650 r180 top
ZZ2 "These assemblies are ESD sensitive, ESD precautions shall be observed." AssemblyNote 3260,6550 r90 top
ZZ3 "These assemblies must be clean and free from flux and all contaminants. Use of no clean flux is not acceptable." AssemblyNote 3260,6440 r90 top
ZZ4 "These assemblies must comply with workmanship standards IPC-A-610 Class 2, unless otherwise specified." AssemblyNote 3260,6340 r90 top

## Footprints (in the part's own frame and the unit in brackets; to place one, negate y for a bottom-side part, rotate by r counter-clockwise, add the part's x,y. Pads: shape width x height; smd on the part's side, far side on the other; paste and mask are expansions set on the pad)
0402 [mm] "0402 from SM-752 data"
  rect 0.8x0.6 smd: 1(-0.6,0) 2(0.6,0)
  silkscreen extent -1.22,-0.52 1.22,0.52, body extent -0.55,-0.3 0.55,0.3, height 0.6
0603 [mm] "0603 from SM-752 data"
  rect 1x0.95 smd: 1(-0.8,0) 2(0.8,0)
  silkscreen extent -1.52,-0.69 1.52,0.69, body extent -0.87,-0.47 0.87,0.47, height 1
0805_HV [mil] "0805 with 30mil clearance between pads"
  rect 50x63 smd: 1(-40,0) 2(40,0)
  silkscreen extent -74,-40 74,40, body extent -43,-29 43,29, height 57
1206 [mm] "1206 from SM-752 data"
  rect 1.3x1.85 smd: 1(-1.45,0) 2(1.45,0)
  silkscreen extent -2.4,-1.21 2.4,1.21, body extent -1.7,-0.9 1.7,0.9, height 1.35
1210_280 [mm] "SMD, 2-Leads, Body 3.6x2.8mm, Height 2.8mm"
  rect 1.1x2.2 smd: 1(-1.65,0) 2(1.65,0)
  silkscreen extent -0.84,-1.4 0.84,1.4, body extent -1.8,-1.4 1.8,1.4, height 2.8
2010 [mm] "Chip Capacitor, Body 5.08x2.54mm, IPC Medium Density"
  rect 1.6x2.7 smd: 1(-2.3,0) 2(2.3,0)
  silkscreen extent -3.42,-1.65 3.42,1.65, body extent -2.73,-1.45 2.73,1.45, height 1.66
AssemblyNote [mil] "Assembly Note"
AssemblyNoteLabel [mil] "Assembly Note for PCB Labels"
CONN_5-146261-1 [mm] "Sullins"
  rect 1.5x1.5 hole 1.02: 1(-1.27,0)
  round 1.5 hole 1.02: 2(1.27,0)
  silkscreen extent -3.68,-1.27 2.54,1.27, body extent -2.51,-1.27 2.51,1.27, height 10.87
DBV0005A_N [mm] "SOT23, 5-Leads, Body 2.9x1.6mm, Pitch 0.95mm, Lead Span 2.8mm, IPC Medium Density"
  rrect17% 1x0.6 smd: 1(-1.375,0.95) 2(-1.375,0) 3(-1.375,-0.95) 4(1.375,-0.95) 5(1.375,0.95)
  silkscreen extent -1.63,-1.55 0.38,1.55, body extent -1.42,-1.46 1.42,1.46, height 1.09
DBV0006A_N [mm] "SOT23, 6-Leads, Body 2.9x1.6mm, Pitch 0.95mm, Lead Span 2.8mm, IPC Medium Density"
  rrect17% 1x0.6 smd: 1(-1.375,0.95) 2(-1.375,0) 3(-1.375,-0.95) 4(1.375,-0.95) 5(1.375,0) 6(1.375,0.95)
  silkscreen extent -1.68,-1.55 0.5,1.55, body extent -1.42,-1.46 1.42,1.46, height 1.12
DGN0008D_L [mm] "TSOP, 8-Leads, Body 3x3mm, Pitch 0.65mm, Thermal Pad 1.89x1.57mm, IPC High Density"
  rrect100% 1.15x0.45 smd: 1(-2.125,0.975) 2(-2.125,0.325) 3(-2.125,-0.325) 4(-2.125,-0.975) 5(2.125,-0.975) 6(2.125,-0.325) 7(2.125,0.325) 8(2.125,0.975)
  rrect6% 1.57x1.89 smd: 9(0,0)
  silkscreen extent -2.58,-1.55 0.95,1.55, body extent -2.46,-1.5 2.46,1.5, height 1.1
ESD_Overlay_Large [mil]
  silkscreen extent -254,-219 250,219
FCC_disclaimer [mil]
Fiducial10-20 [mm]
  round 1 smd mask+0.5: 1(0,0)
  Top Layer keep-out circle w1.178: c0,0 r0.5
Harwin_M7582-05 [mil] "Single Operation 2.54mm Pitch Open Top Jumper Socket"
  body extent -98,-47 98,47, height 236
Keystone5000 [mil] "For Keystone 500x miniature loop terminals"
  round 80 hole 40: 1(0,0)
  silkscreen extent -52,-52 52,52, body extent -49,-49 49,49, height 182
Keystone5002 [mil] "For Keystone 500x miniature loop terminals"
  round 80 hole 40: 1(0,0)
  silkscreen extent -52,-52 52,52, body extent -49,-49 49,49, height 182
Keystone_1902C [mil] "Hex Standoff, 4-40 threaded, nylon"
  round 1 on Mech4: 0(0,0)
  body extent -145,-126 146,126, height 501
KW_DPLS32_EC_White [mm] "SMD, 2-Leads, Body 4x1.4mm"
  rect 0.6x0.8 smd paste-0.05 mask+0: 1(-1.35,0)
  rect 2.1x0.8 smd paste-0.4 mask+0: 2(0.6,0)
  rect 0.8x0.7 on Top Paste: ""(0,0) ""(1.15,0)
  Top Layer region: 2,0.75 1.4,0.75 1.4,-0.75 2,-0.75
  Top Layer region: -2,-0.75 -1.4,-0.75 -1.4,0.75 -2,0.75
  silkscreen extent -2,-1.1 2.8,1.1, body extent -2.05,-0.75 2.05,0.75, height 0.75
Label_650x200 [mil] "Thermal Transfer Label"
  round 1 on Mech13: 0(0,0)
  silkscreen extent -325,-100 325,100, body extent -325,-100 325,100, height 1
LB_T673_Blue [mm] "SMD, 2-Leads, Body 3.2x2.8mm"
  rect 2.6x1.5 smd mask+0: 1(0,1.5) 2(0,-1.5)
  silkscreen extent -1.7,-2.9 1.7,2.2, body extent -1.5,-1.85 1.5,1.85, height 2.1
LED_LTST-C170_Red [mm] "LITE-ON"
  rect 1.2x1.2 smd: 1(-1.05,0) 2(1.05,0)
  silkscreen extent -1.6,-1 2.2,1, body extent -1.05,-0.67 1.05,0.67, height 1.1
LG_T67K_Green [mm] "SMD, 2-Leads, Body 3.2x2.8mm"
  rect 2.6x1.5 smd mask+0: 1(0,1.5) 2(0,-1.5)
  silkscreen extent -1.7,-2.9 1.7,2.2, body extent -1.5,-1.85 1.5,1.85, height 2.1
LS_T67K_Red [mm] "SMD, 2-Leads, Body 3.2x2.8mm"
  rect 2.6x1.5 smd mask+0: 1(0,1.5) 2(0,-1.5)
  silkscreen extent -1.7,-2.9 1.7,2.2, body extent -1.5,-1.85 1.5,1.85, height 2.1
LY_T67K_Yellow [mm] "SMD, 2-Leads, Body 3.2x2.8mm"
  rect 2.6x1.5 smd mask+0: 1(0,1.5) 2(0,-1.5)
  silkscreen extent -1.7,-2.9 1.7,2.2, body extent -1.5,-1.85 1.5,1.85, height 2.1
Net-Tie_50milWide_30milLong [mil] "50mil net tie, no solder mask opening, no solder paste"
  rect 30x50 smd paste-20 mask-20: 1(-15,0) 2(15,0)
"NY PMS 440 0025 PH" [mm] "4-40 nylon screw and mounting hole"
  round 8 hole 3.2: 1(0,0)
  body extent -3.3,-3.3 3.3,3.3, height 2.69
Pb-Free_Overlay_Small [mil]
  silkscreen extent -46,-46 46,46
Phoenix_1759017 [mm] "Header (Shrouded), 5.08mm, 2x1, R/A, TH"
  rect 1.9x1.9 hole 1.4: 1(-2.54,0)
  round 1.9 hole 1.4: 2(2.54,0)
  silkscreen extent -5.6,-10 5.08,2, body extent -5.08,-10 5.08,2, height 8.6
PowerDI3333-8 [mm] "SMD, 8-Leads, Body 3.3x3.3mm, Pitch 0.65mm"
  rect 0.7x0.42 smd: 1(-1.5,0.975) 2(-1.5,0.325) 3(-1.5,-0.325) 4(-1.5,-0.975) 5(1.5,-0.975) 6(1.5,-0.325) 7(1.5,0.325) 8(1.5,0.975)
  rect 1.55x2.37 smd: 9(0.375,0)
  silkscreen extent -1.68,-1.68 1.68,1.9, body extent -1.68,-1.68 1.68,1.68, height 0.86
PWP0016G_L [mm] "TSOP, 16-Leads, Body 5x4.4mm, Pitch 0.65mm, Thermal Pad 2.41x3.29 mm, IPC High Density"
  rrect25% 1.2x0.4 smd: 1(-2.85,2.275) 2(-2.85,1.625) 3(-2.85,0.975) 4(-2.85,0.325) 5(-2.85,-0.325) 6(-2.85,-0.975) 7(-2.85,-1.625) 8(-2.85,-2.275) 9(2.85,-2.275) 10(2.85,-1.625) 11(2.85,-0.975) 12(2.85,-0.325) 13(2.85,0.325) 14(2.85,0.975) 15(2.85,1.625) 16(2.85,2.275)
  rrect6% 3.4x5 smd paste-1.7 mask-1.7: 17(0,0)
  rrect4% 2.41x3.29 on Bottom Paste: 17(0,0)
  rrect4% 2.41x3.29 on Bottom Solder: 17(0,0)
  silkscreen extent -2,-2.55 1.5,2.6, body extent -3.21,-2.5 3.21,2.5, height 0.99
PWP0020D_M [mm] "SOP, 20-Leads, Body 6.4x4.4mm, Pitch 0.65mm, Thermal Pad 2x3mm, IPC Low Density"
  rrect22% 1.6x0.45 smd: 1(-3.05,2.925) 2(-3.05,2.275) 3(-3.05,1.625) 4(-3.05,0.975) 5(-3.05,0.325) 6(-3.05,-0.325) 7(-3.05,-0.975) 8(-3.05,-1.625) 9(-3.05,-2.275) 10(-3.05,-2.925) 11(3.05,-2.925) 12(3.05,-2.275) 13(3.05,-1.625) 14(3.05,-0.975) 15(3.05,-0.325) 16(3.05,0.325) 17(3.05,0.975) 18(3.05,1.625) 19(3.05,2.275) 20(3.05,2.925)
  rrect6% 3.4x6.5 smd paste-2 mask-2: 21(0,0)
  rrect4% 2.4x3.7 on Bottom Paste: 21(0,0)
  rrect4% 2.4x3.7 on Bottom Solder: 21(0,0)
  silkscreen extent -3.75,-3.3 1.5,3.4, body extent -3.21,-3.25 3.21,3.25, height 1
PWP0028C_N [mm] "TSOP, 28-Leads, Body 9.7x4.4mm, Pitch 0.65mm, Exposed Pad, IPC Medium Density"
  rrect22% 1.4x0.45 smd: 1(-2.95,4.225) 2(-2.95,3.575) 3(-2.95,2.925) 4(-2.95,2.275) 5(-2.95,1.625) 6(-2.95,0.975) 7(-2.95,0.325) 8(-2.95,-0.325) 9(-2.95,-0.975) 10(-2.95,-1.625) 11(-2.95,-2.275) 12(-2.95,-2.925) 13(-2.95,-3.575) 14(-2.95,-4.225) 15(2.95,-4.225) 16(2.95,-3.575) 17(2.95,-2.925) 18(2.95,-2.275) 19(2.95,-1.625) 20(2.95,-0.975) 21(2.95,-0.325) 22(2.95,0.325) 23(2.95,0.975) 24(2.95,1.625) 25(2.95,2.275) 26(2.95,2.925) 27(2.95,3.575) 28(2.95,4.225)
  rrect3% 3.4x9.7 smd paste-1.7 mask-1.7: 29(0,0)
  rrect3% 3.1x5.18 on Bottom Paste: 29(0,0)
  rrect3% 3.1x5.18 on Bottom Solder: 29(0,0)
  silkscreen extent -3.5,-4.9 2,4.9, body extent -3.2,-4.85 3.2,4.85, height 1.13
RNX0012A [mm]
  rrect57% 0.7x0.35 smd paste-0.05 mask-0.05: 1(-0.9,1.125) 2(-0.9,0.475) 10(0.9,0.475) 11(0.9,1.125)
  rrect40% 0.6x0.25 smd: 3(-0.9,-0.175) 4(-0.9,-0.675) 8(0.9,-0.7) 9(0.9,-0.2)
  rrect40% 0.25x0.6 smd: 5(-0.5,-1.4) 6(0,-1.4) 7(0.5,-1.4)
  rrect40% 0.25x0.812 on Bottom Paste: 12(0,0.28) 12(0,1.295)
  rrect57% 0.35x1.925 smd paste-0.175 mask-0.05: 12(0,0.788)
  silkscreen extent -1.15,-1.65 1.15,1.65, body extent -1.05,-1.55 1.05,1.55, height 1.02
RUM0016C [mm] "QFN, 16-Leads, Body 4x4mm, Pitch 0.65mm, Thermal Pad 2.3x2.3mm, TI Recommended"
  rrect33% 0.75x0.3 smd: 1(-1.825,0.975) 2(-1.825,0.325) 3(-1.825,-0.325) 4(-1.825,-0.975) 9(1.825,-0.975) 10(1.825,-0.325) 11(1.825,0.325) 12(1.825,0.975)
  rrect33% 0.3x0.75 smd: 5(-0.975,-1.825) 6(-0.325,-1.825) 7(0.325,-1.825) 8(0.975,-1.825) 13(0.975,1.825) 14(0.325,1.825) 15(-0.325,1.825) 16(-0.975,1.825)
  rrect10% 1.02x1.02 on Bottom Paste: 17(-0.61,-0.61) 17(-0.61,0.61) 17(0.61,-0.61) 17(0.61,0.61)
  rrect4% 2.3x2.3 smd paste-1.35: 17(0,0)
  rrect36% 0.725x0.275 on Bottom Paste: A1(-1.837,1.613) A2(-1.837,-1.613) A3(1.837,-1.613) A4(1.837,1.613)
  rrect33% 0.725x0.3 smd paste-0.15: A1(-1.837,1.625) A2(-1.837,-1.625) A3(1.837,-1.625) A4(1.837,1.625)
  rrect36% 0.275x0.725 on Bottom Paste: A1(-1.613,1.837) A2(-1.613,-1.837) A3(1.613,-1.837) A4(1.613,1.837)
  Top Layer region: 1.775,1.525 1.775,2.15 1.771,2.169 1.76,2.185 1.744,2.196 1.725,2.2 1.725,2.2 1.525,2.2 1.506,2.196 1.49,2.185 1.479,2.169 1.475,2.15 1.475,2.15 1.475,1.525 1.479,1.506 1.49,1.49 1.506,1.479 1.525,1.475 1.525,1.475 1.725,1.475 1.744,1.479 1.76,1.49 1.771,1.506 1.775,1.525
  Top Layer region: 1.775,-1.525 1.775,-2.15 1.771,-2.169 1.76,-2.185 1.744,-2.196 1.725,-2.2 1.725,-2.2 1.525,-2.2 1.506,-2.196 1.49,-2.185 1.479,-2.169 1.475,-2.15 1.475,-2.15 1.475,-1.525 1.479,-1.506 1.49,-1.49 1.506,-1.479 1.525,-1.475 1.525,-1.475 1.725,-1.475 1.744,-1.479 1.76,-1.49 1.771,-1.506 1.775,-1.525
  Top Layer region: -1.775,-1.525 -1.775,-2.15 -1.771,-2.169 -1.76,-2.185 -1.744,-2.196 -1.725,-2.2 -1.725,-2.2 -1.525,-2.2 -1.506,-2.196 -1.49,-2.185 -1.479,-2.169 -1.475,-2.15 -1.475,-2.15 -1.475,-1.525 -1.479,-1.506 -1.49,-1.49 -1.506,-1.479 -1.525,-1.475 -1.525,-1.475 -1.725,-1.475 -1.744,-1.479 -1.76,-1.49 -1.771,-1.506 -1.775,-1.525
  Top Layer region: -1.775,1.525 -1.775,2.15 -1.771,2.169 -1.76,2.185 -1.744,2.196 -1.725,2.2 -1.725,2.2 -1.525,2.2 -1.506,2.196 -1.49,2.185 -1.479,2.169 -1.475,2.15 -1.475,2.15 -1.475,1.525 -1.479,1.506 -1.49,1.49 -1.506,1.479 -1.525,1.475 -1.525,1.475 -1.725,1.475 -1.744,1.479 -1.76,1.49 -1.771,1.506 -1.775,1.525
  silkscreen extent -2.45,-2.23 2.23,2.22, body extent -2,-2 2,2, height 0.8
SM_RADIAL_D [mm] "6.3 x 5.8mm:  Panasonic D"
  rect 3.2x1.6 smd: 1(-2.5,0) 2(2.5,0)
  silkscreen extent -3.4,-3.4 3.4,3.4, body extent -3.4,-3.4 3.4,3.4, height 6.1
SM_RADIAL_F [mm] "8 x 10.2mm:  Panasonic F"
  rect 4x2 smd: 1(-3.55,0) 2(3.55,0)
  silkscreen extent -4.25,-4.25 4.25,4.25, body extent -4.25,-4.25 4.25,4.25, height 10.5
SMA [mm] "Molded Diode, 2-Leads, Body 4.3x2.6mm, IPC Medium Density, based on OnSemi component dimensions and land pattern"
  rect 2x2 smd: 1(-2,0) 2(2,0)
  silkscreen extent -3.66,-1.57 2.79,1.57, body extent -2.6,-1.3 2.6,1.3, height 2.42
SMB [mil] "Molded Diode, 2-Leads, Body 5.4x3.6mm, IPC Medium Density, based on OnSemi component dimensions"
  rect 85x107.99 smd: 1(-87.01,0) 2(87.01,0)
  silkscreen extent -155,-82 125,82, body extent -106,-71 106,71, height 91
Sullins_PBC02SAAN [mm] "Sullins 100mil, 1x2, 230 mil above insulator"
  rect 1.65x1.65 hole 1.016: 1(0,1.27)
  round 1.65 hole 1.016: 2(0,-1.27)
  silkscreen extent -1.37,-2.54 1.27,3.1, body extent -1.27,-2.54 1.27,2.54, height 8.38
SULLINS_PEC10DAAN [mm] "SULLINS"
  rrect50% 1.55x1.55 hole 1.016: 1(-1.27,11.43)
  round 1.55 hole 1.016: 2(1.27,11.43) 3(-1.27,8.89) 4(1.27,8.89) 5(-1.27,6.35) 6(1.27,6.35) 7(-1.27,3.81) 8(1.27,3.81) 9(-1.27,1.27) 10(1.27,1.27) 11(-1.27,-1.27) 12(1.27,-1.27) 13(-1.27,-3.81) 14(1.27,-3.81) 15(-1.27,-6.35) 16(1.27,-6.35) 17(-1.27,-8.89) 18(1.27,-8.89) 19(-1.27,-11.43) 20(1.27,-11.43)
  silkscreen extent -2.9,-12.7 2.54,12.7, body extent -2.54,-12.7 2.54,12.7, height 8.38
SW_219-4MST [mm] "SMT, 8-Leads, Body 11.63x6.7mm, Pitch 2.54mm"
  rect 2.44x1.13 smd: 1(-4.3,3.81) 2(-4.3,1.27) 3(-4.3,-1.27) 4(-4.3,-3.81) 5(4.3,-3.81) 6(4.3,-1.27) 7(4.3,1.27) 8(4.3,3.81)
  silkscreen extent -3.7,-5.82 3.35,5.82, body extent -4.95,-5.82 4.95,5.82, height 4.32
TO-277A [mm] "Vishay"
  rect 1.4x1.27 smd: 1(-1.04,1.83) 2(1.04,1.83)
  rect 4.72x4.8 smd: 3(0,-1.883)
  silkscreen extent -2.7,1.45 -2.4,1.75, body extent -2.35,-4.2 2.4,2.45, height 1.2
TRANS_NXP_LFPAK33 [mm] "NXP"
  rect 0.83x0.4 smd paste-0.2 mask+0.05: 1(-1.555,0.975) 2(-1.555,0.325) 3(-1.555,-0.325) 4(-1.555,-0.975)
  rect 1.85x2.25 smd paste-1 mask+0.05: 5(0.385,0)
  Top Layer region: 1.929,-0.775 1.929,-1.175 1.179,-1.175 1.179,-0.775
  Top Layer region: 1.93,-0.125 1.93,-0.525 1.18,-0.525 1.18,-0.125
  Top Layer region: 1.93,0.525 1.93,0.125 1.18,0.125 1.18,0.525
  Top Layer region: 1.93,1.174 1.93,0.774 1.18,0.774 1.18,1.174
  silkscreen extent -1.4,-1.85 1.6,1.85, body extent -1.7,-1.7 1.7,1.7, height 0.91
VISHAY_TEMT6200FX01 [mm] "SMD, 2-Leads, Body 2x1.25mm"
  rect 1x1.45 smd: 1(-0.8,0) 2(0.8,0)
  silkscreen extent 1.63,-0.5 1.83,0.5, body extent -1,-0.63 1,0.63, height 0.85
WE-PD2-S [mm] "WURTH"
  rrect50% 1.75x4.5 smd: 1(-1.625,0) 2(1.625,0)
  Top Layer region: -1.375,2.25 -0.75,2.25 -0.75,-2.25 -1.375,-2.25
  Top Layer region: 1.375,-2.25 0.75,-2.25 0.75,2.25 1.375,2.25
  silkscreen extent -0.4,-2.1 0.4,2.12, body extent -2.25,-2 2.25,2, height 3.18
WE-PD_1030 [mm] "WERTH"
  rect 2x3.5 smd: 1(-4.5,0) 2(4.5,0)
  silkscreen extent -5,-5 5,5, body extent -5,-5 5,5, height 2.7
WE-TPC_4828 [mm] "Wurth Elektronik recommended land pattern"
  rect 0.5x0.5 smd: 1(-2.35,0) 2(2.325,0)
  Top Layer region: 0.75,1.64 1.005,1.504 1.279,1.279 1.504,1.005 1.671,0.692 1.774,0.353 1.809,0 1.774,-0.353 1.671,-0.692 1.504,-1.005 1.279,-1.279 1.005,-1.504 0.75,-1.64 0.75,-2.65 2.75,-2.65 2.75,2.65 0.75,2.65
  Top Layer region: -0.75,1.64 -1.005,1.504 -1.279,1.279 -1.504,1.005 -1.671,0.692 -1.774,0.353 -1.809,0 -1.774,-0.353 -1.671,-0.692 -1.504,-1.005 -1.279,-1.279 -1.005,-1.504 -0.75,-1.64 -0.75,-2.65 -2.75,-2.65 -2.75,2.65 -0.75,2.65
  silkscreen extent -0.5,-2.6 0.5,2.63, body extent -2.5,-2.5 2.5,2.5, height 2
XEL4020 [mm] "SMD, 2-Leads, Body 4x4mm, Pitch 2.37mm"
  rrect10% 0.98x3.7 smd: 1(-1.185,0) 2(1.185,0)
  silkscreen extent -2.3,-2.3 2.3,2.3, body extent -2.15,-2.15 2.15,2.15, height 2.1

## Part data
C1 C54: library part CMP-0006357-2, "CAP, CERM, 2200 pF, 50 V, +/- 10%, X7R, AEC-Q200 Grade 1, 0402", Cap_Case=0402, Manufacturer=MuRata, PartNumber=GCM155R71H222KA37D, Supplier Part Number 1=490-4914-1-ND, TempCo=X7R, Tolerance_%=10%, Value1=Unknown, Value2=50V, ValueDisplayed=2200pF
C2 C3 C4 C5 C6 C9 C12 C20 C29 C31 C55 C56 C57 C58 C59 C60 C64 C68 C75: library part CMP-0009258-2, "CAP, CERM, 10 uF, 50 V, +/- 10%, X7R, AEC-Q200 Grade 1, 1210", Cap_Case=1210, Manufacturer="Taiyo Yuden", Supplier Part Number 1=587-4326-1-ND, TempCo=X7R, Tolerance_%=10%, Value1=Unknown, Value2=50V, ValueDisplayed=10uF
C7 C10 C13 C15 C21 C28 C37 C38 C42 C44 C46 C48 C50 C52 C62 C69 C76: library part CMP-0006356-2, "CAP, CERM, 0.1 uF, 50 V, +/- 10%, X7R, AEC-Q200 Grade 1, 0402", Cap_Case=0402, Manufacturer=MuRata, Supplier Part Number 1=490-10672-1-ND, TempCo=X7R, Tolerance_%=10%, Value1=Unknown, Value2=50V, ValueDisplayed=0.1uF
C8: library part CMP-0011177-2, "CAP, AL, 100 uF, 50 V, +/- 20%, 0.34 ohm, AEC-Q200 Grade 2, SMD", Cap_Case=F, Manufacturer=Panasonic, Supplier Part Number 1=PCE3809CT-ND, Tolerance_%=20%, Value1="0.34 ohm", Value2=50V, ValueDisplayed=100uF
C11: "CAP, CERM, 2.2 µF, 50 V, +/- 10%, X5R, 0805", Cap_Case=0805, Manufacturer=TDK, Supplier Part Number 1=445-5976-1-ND, TempCo=X5R, Tolerance_%=10, Value1=Unknown, Value2=50V, ValueDisplayed=2.2µF
C14: library part CMP-0006673-2, "CAP, CERM, 1000 pF, 50 V, +/- 10%, X7R, 0402", Cap_Case=0402, Manufacturer=MuRata, Supplier Part Number 1=490-1303-1-ND, TempCo=X7R, Tolerance_%=10%, Value1=Unknown, Value2=50V, ValueDisplayed=1000pF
